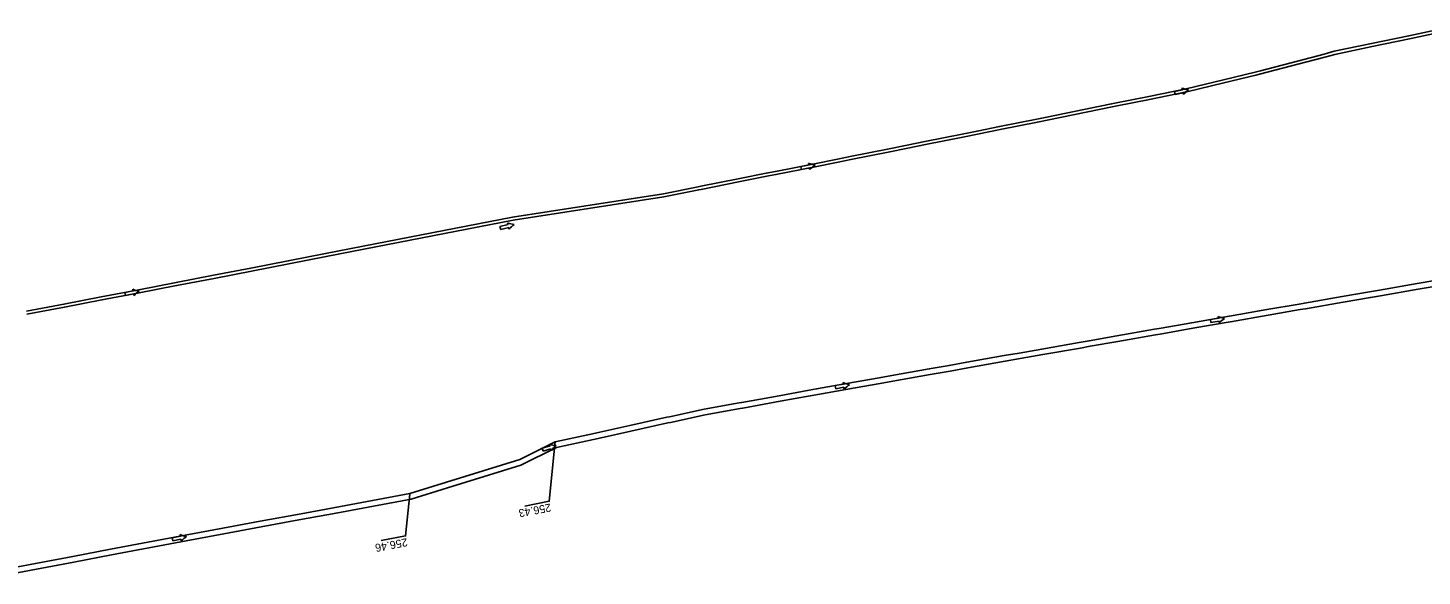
# Model space of a CAD drawing. Extents: x -1 to 65640748, y -22 to 5530284.
# Drawn here: x 6560968.5 to 6561151.5, y 5529328.1 to 5529400.1 of the extents above; entities that cross this region are included whole.
import ezdxf

# ---------------------------------------------------------------- set-up
doc = ezdxf.new("R2010")
doc.units = 0
for name, color, linetype in [('TOR_PS_OPIS_O-opisy rurociagow', 7, 'Continuous'), ('TOR_PS_OPIS_T-INFO', 7, 'Continuous'), ('TOR_PS_T-rowy otwarte umocnione', 7, 'Continuous')]:
    doc.layers.add(name, color=color, linetype=linetype)

msp = doc.modelspace()

# ---------------------------------------------------------------- linework, layer by layer
at = {"layer": 'TOR_PS_OPIS_O-opisy rurociagow'}
for p, q in [((6561120.08, 5529391.96), (6561119.01, 5529391.71)), ((6561120.08, 5529391.96), (6561119.01, 5529391.71)), ((6561119.01, 5529391.71), (6561119.11, 5529391.32)), ((6561119.01, 5529391.71), (6561119.11, 5529391.32)), ((6561119.11, 5529391.32), (6561120.17, 5529391.57)), ((6561120.17, 5529391.57), (6561119.11, 5529391.32)), ((6561071.06, 5529382.1), (6561069.99, 5529381.88)), ((6561071.06, 5529382.1), (6561069.99, 5529381.88)), ((6561069.99, 5529381.88), (6561070.06, 5529381.49)), ((6561069.99, 5529381.88), (6561070.06, 5529381.49)), ((6561070.06, 5529381.49), (6561071.14, 5529381.7)), ((6561071.14, 5529381.7), (6561070.06, 5529381.49)), ((6561031.56, 5529374.25), (6561030.5, 5529373.99)), ((6561031.56, 5529374.25), (6561030.5, 5529373.99)), ((6561030.5, 5529373.99), (6561030.6, 5529373.6)), ((6561030.5, 5529373.99), (6561030.6, 5529373.6)), ((6561030.6, 5529373.6), (6561031.66, 5529373.86)), ((6561031.66, 5529373.86), (6561030.6, 5529373.6)), ((6560982.35, 5529365.54), (6560981.28, 5529365.33)), ((6560982.35, 5529365.54), (6560981.28, 5529365.33)), ((6560981.28, 5529365.33), (6560981.35, 5529364.94)), ((6560981.28, 5529365.33), (6560981.35, 5529364.94)), ((6560981.35, 5529364.94), (6560982.43, 5529365.15)), ((6560982.43, 5529365.15), (6560981.35, 5529364.94)), ((6561124.81, 5529361.97), (6561123.74, 5529361.78)), ((6561124.81, 5529361.97), (6561123.74, 5529361.78)), ((6561123.74, 5529361.78), (6561123.81, 5529361.39)), ((6561123.74, 5529361.78), (6561123.81, 5529361.39)), ((6561123.81, 5529361.39), (6561124.88, 5529361.57)), ((6561124.88, 5529361.57), (6561123.81, 5529361.39)), ((6561075.57, 5529353.28), (6561074.5, 5529353.09)), ((6561075.57, 5529353.28), (6561074.5, 5529353.09)), ((6561074.5, 5529353.09), (6561074.57, 5529352.69)), ((6561074.5, 5529353.09), (6561074.57, 5529352.69)), ((6561074.57, 5529352.69), (6561075.64, 5529352.89)), ((6561075.64, 5529352.89), (6561074.57, 5529352.69)), ((6561037.07, 5529345.19), (6561036.03, 5529344.87)), ((6561037.07, 5529345.19), (6561036.03, 5529344.87)), ((6561036.03, 5529344.87), (6561036.15, 5529344.48)), ((6561036.03, 5529344.87), (6561036.15, 5529344.48)), ((6561036.15, 5529344.48), (6561037.19, 5529344.81)), ((6561037.19, 5529344.81), (6561036.15, 5529344.48)), ((6560988.56, 5529333.31), (6560987.49, 5529333.11)), ((6560988.56, 5529333.31), (6560987.49, 5529333.11)), ((6560987.49, 5529333.11), (6560987.56, 5529332.72)), ((6560987.49, 5529333.11), (6560987.56, 5529332.72)), ((6560987.56, 5529332.72), (6560988.63, 5529332.92)), ((6560988.63, 5529332.92), (6560987.56, 5529332.72))]:
    msp.add_line(p, q, dxfattribs=at)
for points in [[(6561120.01, 5529392.18), (6561120.01, 5529392.18)], [(6561120.21, 5529391.35), (6561120.21, 5529391.35)], [(6561071, 5529382.32), (6561071, 5529382.32)], [(6561071.17, 5529381.48), (6561071.17, 5529381.48)], [(6561031.5, 5529374.47), (6561031.5, 5529374.47)], [(6561031.7, 5529373.64), (6561031.7, 5529373.64)], [(6560982.3, 5529365.76), (6560982.3, 5529365.76)], [(6560982.46, 5529364.92), (6560982.46, 5529364.92)], [(6561124.76, 5529362.19), (6561124.76, 5529362.19)], [(6561124.91, 5529361.35), (6561124.91, 5529361.35)], [(6561075.52, 5529353.5), (6561075.52, 5529353.5)], [(6561075.67, 5529352.66), (6561075.67, 5529352.66)], [(6561037, 5529345.4), (6561037, 5529345.4)], [(6561037.25, 5529344.59), (6561037.25, 5529344.59)], [(6560988.51, 5529333.53), (6560988.51, 5529333.53)], [(6560988.67, 5529332.7), (6560988.67, 5529332.7)]]:
    msp.add_lwpolyline(points, dxfattribs=at)
for centre, radius, start, end in [((6561121.71, 5529396.79), 4.92, 249.765, 260.1468), ((6561120.47, 5529392.19), 0.458, 181.8796, 210.3408), ((6561121.71, 5529396.79), 4.92, 249.765, 260.1468), ((6561120.47, 5529392.19), 0.458, 181.8796, 210.3408), ((6561120.63, 5529391.55), 0.458, 176.6089, 205.0701), ((6561120.63, 5529391.55), 0.458, 176.6089, 205.0701), ((6561123.82, 5529388.01), 4.92, 126.8029, 137.1847), ((6561123.82, 5529388.01), 4.92, 126.8029, 137.1847), ((6561072.88, 5529386.86), 4.92, 247.5902, 257.972), ((6561071.46, 5529382.31), 0.458, 179.7048, 208.166), ((6561072.88, 5529386.86), 4.92, 247.5902, 257.972), ((6561071.46, 5529382.31), 0.458, 179.7048, 208.166), ((6561071.59, 5529381.66), 0.458, 174.4341, 202.8953), ((6561071.59, 5529381.66), 0.458, 174.4341, 202.8953), ((6561074.65, 5529378.01), 4.92, 124.6281, 135.0099), ((6561074.65, 5529378.01), 4.92, 124.6281, 135.0099), ((6561033.18, 5529379.09), 4.92, 250.0475, 260.4294), ((6561031.96, 5529374.49), 0.458, 182.1621, 210.6234), ((6561033.18, 5529379.09), 4.92, 250.0475, 260.4294), ((6561031.96, 5529374.49), 0.458, 182.1621, 210.6234), ((6561035.32, 5529370.32), 4.92, 127.0854, 137.4673), ((6561035.32, 5529370.32), 4.92, 127.0854, 137.4673), ((6561032.11, 5529373.84), 0.458, 176.8915, 205.3527), ((6561032.11, 5529373.84), 0.458, 176.8915, 205.3527), ((6560984.2, 5529370.29), 4.92, 247.2071, 257.5889), ((6560982.75, 5529365.75), 0.458, 179.3216, 207.7829), ((6560984.2, 5529370.29), 4.92, 247.2071, 257.5889), ((6560982.75, 5529365.75), 0.458, 179.3216, 207.7829), ((6560982.88, 5529365.1), 0.458, 174.051, 202.5122), ((6560982.88, 5529365.1), 0.458, 174.051, 202.5122), ((6560985.91, 5529361.42), 4.92, 124.2449, 134.6268), ((6560985.91, 5529361.42), 4.92, 124.2449, 134.6268), ((6561126.75, 5529366.69), 4.92, 246.1948, 256.5767), ((6561125.22, 5529362.17), 0.458, 178.3094, 206.7706), ((6561126.75, 5529366.69), 4.92, 246.1948, 256.5767), ((6561125.22, 5529362.17), 0.458, 178.3094, 206.7706), ((6561125.34, 5529361.52), 0.458, 173.0387, 201.5), ((6561125.34, 5529361.52), 0.458, 173.0387, 201.5), ((6561128.3, 5529357.79), 4.92, 123.2327, 133.6145), ((6561128.3, 5529357.79), 4.92, 123.2327, 133.6145), ((6561077.49, 5529358.01), 4.92, 246.4096, 256.7914), ((6561075.98, 5529353.49), 0.458, 178.5242, 206.9854), ((6561077.49, 5529358.01), 4.92, 246.4096, 256.7914), ((6561075.98, 5529353.49), 0.458, 178.5242, 206.9854), ((6561076.1, 5529352.83), 0.458, 173.2535, 201.7148), ((6561076.1, 5529352.83), 0.458, 173.2535, 201.7148), ((6561079.08, 5529349.11), 4.92, 123.4475, 133.8293), ((6561079.08, 5529349.11), 4.92, 123.4475, 133.8293), ((6561038.4, 5529350.11), 4.92, 253.4434, 263.8252), ((6561037.45, 5529345.45), 0.458, 185.5579, 214.0192), ((6561038.4, 5529350.11), 4.92, 253.4434, 263.8252), ((6561037.45, 5529345.45), 0.458, 185.5579, 214.0192), ((6561041.06, 5529341.48), 4.92, 130.4812, 140.8631), ((6561041.06, 5529341.48), 4.92, 130.4812, 140.8631), ((6561037.65, 5529344.81), 0.458, 180.2873, 208.7485), ((6561037.65, 5529344.81), 0.458, 180.2873, 208.7485), ((6560990.44, 5529338.05), 4.92, 246.8885, 257.2703), ((6560988.97, 5529333.52), 0.458, 179.0031, 207.4643), ((6560990.44, 5529338.05), 4.92, 246.8885, 257.2703), ((6560988.97, 5529333.52), 0.458, 179.0031, 207.4643), ((6560989.09, 5529332.87), 0.458, 173.7324, 202.1937), ((6560989.09, 5529332.87), 0.458, 173.7324, 202.1937), ((6560992.1, 5529329.18), 4.92, 123.9264, 134.3082), ((6560992.1, 5529329.18), 4.92, 123.9264, 134.3082)]:
    msp.add_arc(centre, radius, start, end, dxfattribs=at)
at = {"layer": 'TOR_PS_OPIS_T-INFO'}
for points in [[(6561037.75, 5529345.75), (6561036.97, 5529337.9), (6561033.74, 5529337.28)], [(6561018.67, 5529338.84), (6561018.12, 5529333.36), (6561014.89, 5529332.73)]]:
    msp.add_lwpolyline(points, dxfattribs=at)
at = {"layer": 'TOR_PS_T-rowy otwarte umocnione'}
for points in [[(6561154.68, 5529400.08), (6561149.78, 5529399.05), (6561144.89, 5529398.02), (6561139.99, 5529397), (6561138.68, 5529396.63), (6561135.15, 5529395.69), (6561130.3, 5529394.45), (6561129.63, 5529394.28), (6561125.44, 5529393.25), (6561120.57, 5529392.08), (6561120.55, 5529392.08), (6561115.67, 5529391.08), (6561111.4, 5529390.22), (6561110.77, 5529390.09), (6561105.87, 5529389.1), (6561102.26, 5529388.36), (6561100.97, 5529388.1), (6561096.07, 5529387.11), (6561093.11, 5529386.52), (6561091.16, 5529386.13), (6561086.26, 5529385.14), (6561083.96, 5529384.68), (6561081.36, 5529384.16), (6561076.46, 5529383.18), (6561074.81, 5529382.85), (6561071.55, 5529382.2), (6561066.65, 5529381.22), (6561065.66, 5529381.02), (6561061.74, 5529380.24), (6561056.84, 5529379.27), (6561056.51, 5529379.2), (6561051.94, 5529378.29), (6561032.16, 5529375.23)], [(6561154.75, 5529399.69), (6561149.86, 5529398.66), (6561144.96, 5529397.63), (6561140.07, 5529396.6), (6561138.75, 5529396.24), (6561135.23, 5529395.3), (6561130.37, 5529394.06), (6561129.7, 5529393.89), (6561125.51, 5529392.85), (6561120.64, 5529391.69), (6561120.62, 5529391.68), (6561115.74, 5529390.69), (6561111.48, 5529389.82), (6561110.84, 5529389.7), (6561105.94, 5529388.7), (6561102.33, 5529387.97), (6561101.04, 5529387.71), (6561096.14, 5529386.72), (6561093.18, 5529386.13), (6561091.24, 5529385.73), (6561086.34, 5529384.75), (6561084.04, 5529384.29), (6561081.43, 5529383.76), (6561076.53, 5529382.78), (6561074.89, 5529382.45), (6561071.63, 5529381.8), (6561066.72, 5529380.82), (6561065.74, 5529380.63), (6561061.82, 5529379.85), (6561056.92, 5529378.87), (6561056.59, 5529378.81), (6561052.01, 5529377.9), (6561032.24, 5529374.83)], [(6561032.16, 5529375.23), (6561012.53, 5529371.39), (6561007.62, 5529370.43), (6561002.72, 5529369.48), (6560997.81, 5529368.53), (6560992.9, 5529367.58), (6560987.99, 5529366.63), (6560983.08, 5529365.68), (6560978.17, 5529364.74), (6560973.26, 5529363.79), (6560968.35, 5529362.85)], [(6561032.24, 5529374.83), (6561012.61, 5529371), (6561007.7, 5529370.04), (6561002.79, 5529369.09), (6560997.88, 5529368.13), (6560992.97, 5529367.18), (6560988.06, 5529366.23), (6560983.15, 5529365.29), (6560978.25, 5529364.34), (6560973.33, 5529363.4), (6560968.42, 5529362.46)], [(6561155.79, 5529367.34), (6561150.86, 5529366.49), (6561145.94, 5529365.64), (6561144.6, 5529365.41), (6561141.01, 5529364.79), (6561136.08, 5529363.93), (6561135.4, 5529363.81), (6561131.16, 5529363.07), (6561126.23, 5529362.22), (6561126.21, 5529362.21), (6561121.3, 5529361.36), (6561117.02, 5529360.61), (6561116.38, 5529360.49), (6561111.45, 5529359.63), (6561107.82, 5529358.99), (6561106.53, 5529358.76), (6561101.6, 5529357.9), (6561098.64, 5529357.37), (6561096.68, 5529357.03), (6561091.76, 5529356.16), (6561089.45, 5529355.75), (6561086.83, 5529355.28), (6561081.91, 5529354.41), (6561080.26, 5529354.11), (6561076.99, 5529353.53), (6561072.06, 5529352.65), (6561071.07, 5529352.48), (6561067.14, 5529351.77), (6561062.22, 5529350.89), (6561061.89, 5529350.83), (6561057.3, 5529350.01), (6561052.74, 5529349), (6561052.41, 5529348.93), (6561047.53, 5529347.85), (6561043.62, 5529346.99), (6561042.64, 5529346.77), (6561037.76, 5529345.69)], [(6561155.93, 5529366.61), (6561151, 5529365.75), (6561146.08, 5529364.9), (6561144.74, 5529364.67), (6561141.15, 5529364.05), (6561136.22, 5529363.19), (6561135.54, 5529363.08), (6561131.3, 5529362.34), (6561126.37, 5529361.48), (6561126.35, 5529361.48), (6561121.44, 5529360.62), (6561117.16, 5529359.87), (6561116.52, 5529359.76), (6561111.59, 5529358.89), (6561107.96, 5529358.26), (6561106.67, 5529358.03), (6561101.74, 5529357.16), (6561098.77, 5529356.64), (6561096.82, 5529356.29), (6561091.9, 5529355.42), (6561089.59, 5529355.01), (6561086.97, 5529354.55), (6561082.05, 5529353.67), (6561080.4, 5529353.38), (6561077.13, 5529352.79), (6561072.2, 5529351.92), (6561071.21, 5529351.74), (6561067.28, 5529351.04), (6561062.36, 5529350.15), (6561062.03, 5529350.09), (6561057.44, 5529349.27), (6561052.88, 5529348.26), (6561052.55, 5529348.19), (6561047.67, 5529347.11), (6561043.76, 5529346.25), (6561042.78, 5529346.03), (6561037.9, 5529344.95)], [(6561037.76, 5529345.69), (6561033.11, 5529343.38), (6561028.3, 5529341.9), (6561023.49, 5529340.41), (6561018.69, 5529338.92), (6561013.77, 5529338.01), (6561008.85, 5529337.1), (6561003.94, 5529336.18), (6560999.02, 5529335.27), (6560994.11, 5529334.35), (6560989.19, 5529333.43), (6560984.28, 5529332.51), (6560979.37, 5529331.59), (6560974.45, 5529330.66), (6560969.54, 5529329.73), (6560964.62, 5529328.81)], [(6561037.9, 5529344.95), (6561033.25, 5529342.65), (6561028.44, 5529341.16), (6561023.63, 5529339.67), (6561018.83, 5529338.18), (6561013.91, 5529337.27), (6561008.99, 5529336.36), (6561004.08, 5529335.45), (6560999.16, 5529334.53), (6560994.25, 5529333.61), (6560989.33, 5529332.69), (6560984.42, 5529331.77), (6560979.5, 5529330.85), (6560974.59, 5529329.92), (6560969.68, 5529329), (6560964.76, 5529328.07)]]:
    msp.add_lwpolyline(points, dxfattribs=at)

# ---------------------------------------------------------------- texts
at = {"layer": 'TOR_PS_OPIS_T-INFO'}
for s, p in [('256.43', (6561037.1, 5529337.61)), ('256.46', (6561018.26, 5529333.06))]:
    msp.add_text(s, height=1.05, rotation=190.7159, dxfattribs=at).set_placement(p)

doc.saveas('drawing.dxf')
